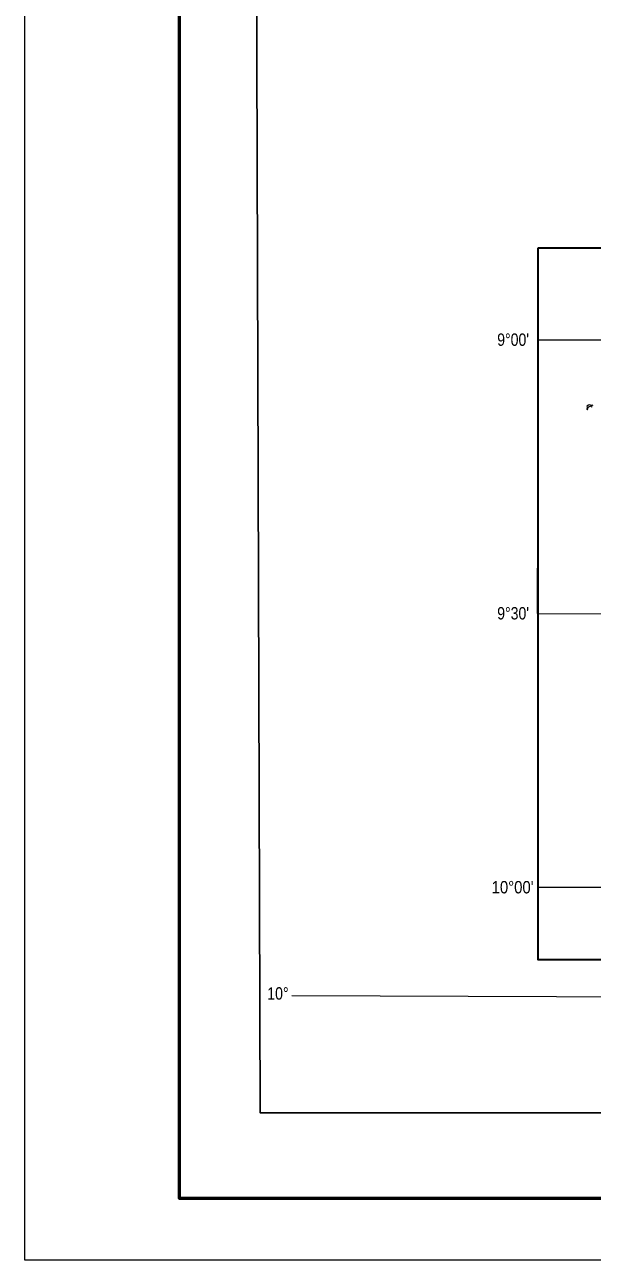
# Model space of a CAD drawing. Extents: x 553962 to 842807, y 8883888 to 9032388.
# Drawn here: x 553962 to 576874, y 8883888 to 8933785 of the extents above; entities that cross this region are included whole.
import ezdxf
from ezdxf.enums import TextEntityAlignment as Align

# ---------------------------------------------------------------- set-up
doc = ezdxf.new("R2010")
doc.units = 0
doc.header["$LTSCALE"] = 200
for name, color, linetype, lineweight in [('1', 7, 'Continuous', 13), ('3', 7, 'Continuous', 80), ('6', 7, 'Continuous', 13)]:
    doc.layers.add(name, color=color, linetype=linetype, lineweight=lineweight)
doc.layers.add('46', color=7, linetype='Continuous')

msp = doc.modelspace()

# ---------------------------------------------------------------- linework, layer by layer
at = {"layer": '1'}
msp.add_lwpolyline([(564751.7, 8894587.5), (664411.9, 8894209.9), (791388.5, 8893536.2)], dxfattribs=at)
at = {"layer": '3', "lineweight": 13}
msp.add_lwpolyline([(842807.3, 9032387.8), (842807.3, 8883887.8), (553961.7, 8883887.8), (553961.7, 9032387.8)], close=True, dxfattribs=at)
at = {"layer": '3', "lineweight": 53}
msp.add_lwpolyline([(840307.3, 9029887.8), (840307.3, 8886387.8), (560211.7, 8886387.8), (560211.7, 9029887.8)], close=True, dxfattribs=at)
at = {"layer": '3', "lineweight": 25}
msp.add_lwpolyline([(563033.9, 9026438.8), (793061.1, 9026438.8), (793495.6, 8889836.8), (563468.3, 8889836.8)], close=True, dxfattribs=at)
at = {"layer": '6'}
msp.add_line((574653.9, 8910009.3), (626625.7, 8909822.1), dxfattribs=at)
at = {"layer": '6', "lineweight": 35}
msp.add_lwpolyline([(574695.3, 8924769.6), (626625.7, 8924769.6), (626625.7, 8896026.7), (574695.3, 8896026.7)], close=True, dxfattribs=at)
at = {"layer": '6'}
for points in [[(585645.8, 8921027.3), (574684.9, 8921064.7), (574653.9, 8910009.3), (585614.8, 8909969.8)], [(585583.8, 8898914.4), (574695.3, 8898953.2), (574695.3, 8896026.7), (585573.6, 8896026.7)]]:
    msp.add_lwpolyline(points, close=True, dxfattribs=at)
for points in [[(574684.9, 8921064.7), (596639.8, 8920989.8), (607636.3, 8920937.2), (626625.7, 8920820.5)], [(576893.7, 8918416.7), (576869.5, 8918413.2), (576826.3, 8918412.8), (576773.5, 8918429.2), (576731.3, 8918425.5), (576706.8, 8918414.9), (576692.2, 8918402.8), (576658.1, 8918382.5), (576657.2, 8918376.5), (576657.2, 8918376.5), (576665.4, 8918346.7), (576665.4, 8918303.4), (576657.6, 8918268.8), (576660.2, 8918260.6), (576669.7, 8918252), (576674.8, 8918251.5), (576696.5, 8918271.9), (576707.8, 8918319.8), (576717.3, 8918337.2), (576738.9, 8918360.9), (576760.9, 8918373.4), (576801.8, 8918378.5), (576835.7, 8918371.3), (576854.4, 8918359.7), (576853.1, 8918356.1), (576875.8, 8918338.5)], [(574695.3, 8898953.2), (596544.3, 8898870.4), (626625.7, 8898710.8)]]:
    msp.add_lwpolyline(points, dxfattribs=at)

# ---------------------------------------------------------------- texts
at = {"layer": '46', "width": 0.85}
msp.add_text('10°', height=500, dxfattribs=at).set_placement((564183.6, 8894414.2), align=Align.CENTER)
at = {"layer": '6'}
for s, width, p in [("9°00'", 0.85, (573677.4, 8920816.3)), ("9°30'", 0.85, (573677.4, 8909766.4)), ("10°00'", 0.9, (573657.3, 8898704.5))]:
    msp.add_text(s, height=500, dxfattribs=dict(at, width=width)).set_placement(p, align=Align.CENTER)

doc.saveas('drawing.dxf')
